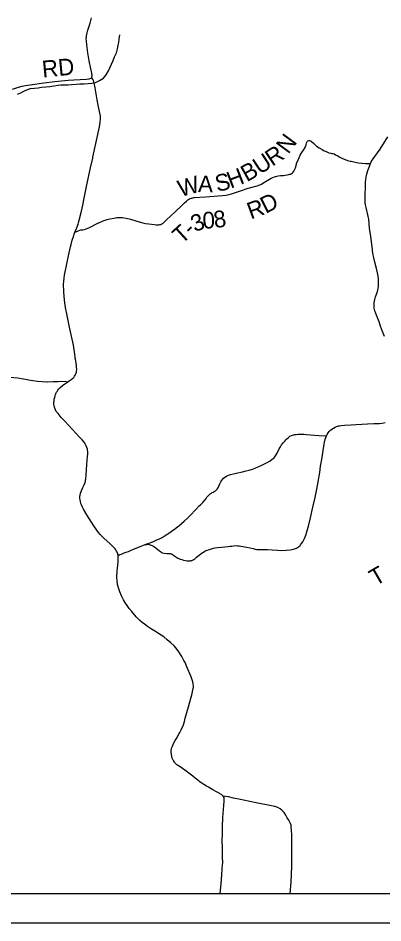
# Model space of a CAD drawing. Extents: x 0 to 34, y 0 to 22.
# Drawn here: x 3.772 to 5.01, y 14.105 to 17.181 of the extents above; entities that cross this region are included whole.
import ezdxf

# ---------------------------------------------------------------- set-up
doc = ezdxf.new("R2010")
doc.units = 0
for name, color, linetype in [('GM_X_County_Road', 7, 'Continuous'), ('GM_X_County_Road_Text', 7, 'Continuous'), ('GM_X_Major_River', 7, 'Continuous'), ('GM_X_State_Route', 7, 'Continuous'), ('GM_X_Township_Road', 7, 'Continuous'), ('GM_X_Township_Road_Text', 7, 'Continuous'), ('SH_Data', 7, 'Continuous')]:
    doc.layers.add(name, color=color, linetype=linetype)

msp = doc.modelspace()

# ---------------------------------------------------------------- linework, layer by layer
at = {"layer": 'GM_X_County_Road'}
msp.add_lwpolyline([(3.7528, 16.9393), (3.7733, 16.9459), (3.7853, 16.9491), (3.7975, 16.9518), (3.8129, 16.9542), (3.859, 16.9605), (3.896, 16.9651), (3.9423, 16.97), (3.9609, 16.9714), (4.0042, 16.9735), (4.0133, 16.9746), (4.017, 16.9757), (4.0195, 16.9769), (4.0216, 16.9792), (4.0225, 16.9812), (4.023, 16.9843), (4.0228, 16.9872), (4.0224, 16.9902), (4.0217, 16.9938), (4.0187, 17.0084), (4.0134, 17.0357), (4.0088, 17.0632), (4.0047, 17.0904), (4.0035, 17.1028), (4.0032, 17.1118), (4.0035, 17.1176), (4.0038, 17.1205), (4.0061, 17.1309), (4.0087, 17.1399), (4.0167, 17.1635), (4.0192, 17.1724), (4.0212, 17.1814)], dxfattribs=at)
at = {"layer": 'GM_X_Major_River'}
msp.add_lwpolyline([(3.7701, 16.9224), (3.7811, 16.9274), (3.7909, 16.9327), (3.8034, 16.9377), (3.8139, 16.9412), (3.8276, 16.9431), (3.8397, 16.9443), (3.8514, 16.9459), (3.8658, 16.9475), (3.8798, 16.9487), (3.8926, 16.9506), (3.9074, 16.9534), (3.9172, 16.9545), (3.9312, 16.9546), (3.9418, 16.9543), (3.9535, 16.9551), (3.9694, 16.9567), (3.9815, 16.9575), (3.9955, 16.9572), (4.0095, 16.9587), (4.0224, 16.9599), (4.0349, 16.9623), (4.0485, 16.9684), (4.0613, 16.9772), (4.0711, 16.9878), (4.079, 17.0015), (4.0839, 17.014), (4.0884, 17.0239), (4.0944, 17.0372), (4.0993, 17.0497), (4.1057, 17.0623), (4.1094, 17.0763), (4.112, 17.0884), (4.1135, 17.0979), (4.1154, 17.1097), (4.1172, 17.1241)], dxfattribs=at)
at = {"layer": 'GM_X_State_Route'}
msp.add_lwpolyline([(5.0158, 16.0988), (5.0089, 16.1158), (5.0021, 16.1335), (4.9971, 16.1482), (4.9904, 16.1659), (4.9862, 16.1764), (4.9827, 16.1858), (4.9807, 16.1946), (4.9801, 16.2007), (4.9799, 16.2068), (4.9803, 16.2129), (4.981, 16.2187), (4.9822, 16.2245), (4.9848, 16.2333), (4.9903, 16.2477), (4.993, 16.2565), (4.9942, 16.2625), (4.995, 16.2685), (4.9955, 16.2778), (4.9954, 16.2871), (4.9948, 16.2956), (4.9938, 16.3034), (4.9915, 16.3152), (4.9877, 16.33), (4.982, 16.351), (4.9786, 16.3662), (4.9759, 16.3816), (4.973, 16.4031), (4.9685, 16.4388), (4.965, 16.4664), (4.9618, 16.4973), (4.9604, 16.5065), (4.9592, 16.5125), (4.9531, 16.5366), (4.9511, 16.5459), (4.9502, 16.552), (4.9496, 16.5611), (4.9495, 16.5766), (4.9504, 16.6108), (4.951, 16.6232), (4.952, 16.6325), (4.9536, 16.6418), (4.9557, 16.6509), (4.9591, 16.6629), (4.9631, 16.6747), (4.9679, 16.6869), (4.9702, 16.692), (4.9731, 16.6976), (4.9765, 16.7028), (4.9821, 16.7104), (4.9916, 16.7226), (5.0005, 16.7353), (5.0271, 16.7772)], dxfattribs=at)
at = {"layer": 'GM_X_Township_Road'}
for points in [[(3.9407, 15.9449), (3.945, 15.9476), (3.9523, 15.9524), (3.9575, 15.9566), (3.9609, 15.9598), (3.9638, 15.9639), (3.9658, 15.9675), (3.968, 15.972), (3.9696, 15.9775), (3.9703, 15.9813), (3.9707, 15.9857), (3.9707, 15.9888), (3.9704, 15.9928), (3.97, 15.9986), (3.9685, 16.0088), (3.9677, 16.0148), (3.9664, 16.0213), (3.9659, 16.0252), (3.9653, 16.0297), (3.9645, 16.0382), (3.9626, 16.0536), (3.96, 16.0689), (3.9559, 16.09), (3.9467, 16.1308), (3.9384, 16.1703), (3.933, 16.1977), (3.9307, 16.2131), (3.9282, 16.2346), (3.9269, 16.2518), (3.9264, 16.2767), (3.9269, 16.286), (3.9281, 16.2983), (3.9294, 16.3076), (3.9369, 16.3455), (3.9425, 16.3724), (3.9502, 16.4034), (3.952, 16.4112), (3.9559, 16.4264), (3.9595, 16.4384), (3.9634, 16.4499), (3.9656, 16.4551), (3.9711, 16.4684), (3.9758, 16.4806), (3.9784, 16.4895), (3.9858, 16.5196), (3.9926, 16.5499), (3.9942, 16.5577), (3.9987, 16.5804), (4.0057, 16.6138), (4.0176, 16.6716), (4.025, 16.7053), (4.0256, 16.708), (4.0478, 16.8114), (4.0504, 16.8267), (4.0519, 16.839), (4.052, 16.8421), (4.0518, 16.8452), (4.0514, 16.8483), (4.0483, 16.8635), (4.0435, 16.8846), (4.04, 16.9027), (4.0329, 16.9435), (4.0295, 16.9594), (4.0272, 16.9687), (4.0255, 16.9735), (4.0236, 16.9767), (4.0216, 16.9792)], [(3.9656, 16.4551), (3.9671, 16.4548), (3.9695, 16.455), (3.9716, 16.4559), (3.9736, 16.4571), (3.9761, 16.4582), (3.9845, 16.4607), (3.9881, 16.4607), (3.9911, 16.4611), (3.9972, 16.4626), (4.003, 16.4647), (4.0116, 16.4684), (4.0449, 16.485), (4.0455, 16.4853), (4.0607, 16.4919), (4.0611, 16.492), (4.0675, 16.4942), (4.0739, 16.4961), (4.0829, 16.4983), (4.0982, 16.5013), (4.1074, 16.5028), (4.1135, 16.5033), (4.1197, 16.5035), (4.1259, 16.5031), (4.1321, 16.5022), (4.1381, 16.5009), (4.1532, 16.497), (4.1718, 16.4914), (4.1829, 16.488), (4.1949, 16.4849), (4.2041, 16.4832), (4.216, 16.4812), (4.2333, 16.4791), (4.2402, 16.4786), (4.2461, 16.4784), (4.2499, 16.4784), (4.2533, 16.479), (4.2564, 16.4798), (4.2592, 16.4811), (4.2644, 16.4844), (4.2668, 16.4864), (4.2715, 16.4905), (4.2758, 16.4949), (4.3051, 16.5225), (4.3274, 16.5439), (4.3363, 16.5525), (4.3431, 16.5589), (4.3479, 16.5628), (4.3505, 16.5645), (4.3532, 16.5661), (4.356, 16.5674), (4.3589, 16.5685), (4.3619, 16.5694), (4.3649, 16.5701), (4.3679, 16.5706), (4.371, 16.571), (4.4081, 16.5733), (4.466, 16.5775), (4.4783, 16.5793), (4.4875, 16.5812), (4.4932, 16.5828), (4.5066, 16.587), (4.5268, 16.5933), (4.5532, 16.6025), (4.583, 16.6112), (4.5918, 16.6142), (4.5975, 16.6166), (4.6029, 16.6195), (4.631, 16.6367), (4.6361, 16.6393), (4.6415, 16.6416), (4.6456, 16.643), (4.6497, 16.644), (4.6549, 16.6449), (4.6629, 16.6456), (4.6725, 16.6464), (4.691, 16.6492), (4.694, 16.6499), (4.6969, 16.651), (4.6998, 16.6526), (4.7034, 16.6553), (4.7056, 16.6577), (4.7073, 16.6603), (4.7088, 16.663), (4.712, 16.6696), (4.7129, 16.6722), (4.7162, 16.6843), (4.7172, 16.687), (4.7231, 16.7014), (4.7292, 16.7148), (4.7325, 16.7208), (4.7375, 16.7273), (4.7408, 16.7325), (4.7457, 16.7409), (4.7468, 16.744), (4.749, 16.7504), (4.7506, 16.7564), (4.7517, 16.7593), (4.7532, 16.7618), (4.7553, 16.764), (4.7581, 16.7652), (4.7611, 16.7652), (4.764, 16.764), (4.7665, 16.7624), (4.7751, 16.7542), (4.7844, 16.7461), (4.7932, 16.7398), (4.8033, 16.7338), (4.8088, 16.731), (4.8171, 16.727), (4.827, 16.7233), (4.8333, 16.7214), (4.8366, 16.7208), (4.8398, 16.7204), (4.8441, 16.7195), (4.8493, 16.7167), (4.8565, 16.7125), (4.8618, 16.7096), (4.8729, 16.7041), (4.8814, 16.7005), (4.8902, 16.6974), (4.8991, 16.6949), (4.9018, 16.6943), (4.9113, 16.6922), (4.9265, 16.6895), (4.9388, 16.688), (4.9512, 16.6871), (4.9605, 16.687), (4.9679, 16.6869)], [(3.7038, 15.9577), (3.7082, 15.9593), (3.7139, 15.9605), (3.7201, 15.9611), (3.7274, 15.9612), (3.7435, 15.9607), (3.7573, 15.9597), (3.7709, 15.9585), (3.7839, 15.9562), (3.797, 15.9534), (3.8144, 15.9501), (3.8375, 15.9472), (3.8533, 15.9452), (3.8681, 15.9447), (3.8702, 15.9446), (3.8904, 15.9457), (3.908, 15.9462), (3.9223, 15.9465), (3.9345, 15.9454), (3.9407, 15.9449)], [(4.4581, 14.2054), (4.4608, 14.2379), (4.4628, 14.2689), (4.4648, 14.2891), (4.466, 14.3025), (4.4662, 14.3108), (4.4658, 14.3278), (4.4651, 14.3589), (4.4649, 14.3864), (4.465, 14.4046), (4.4656, 14.4255), (4.466, 14.439), (4.4669, 14.458), (4.4672, 14.4639), (4.4697, 14.5041), (4.4712, 14.5195), (4.4717, 14.5255), (4.471, 14.5312), (4.4682, 14.536), (4.4656, 14.5389), (4.4629, 14.5407), (4.4555, 14.5452), (4.4538, 14.5462), (4.445, 14.5514), (4.433, 14.5581), (4.4267, 14.5617), (4.4185, 14.5663), (4.4118, 14.5704), (4.4027, 14.5754), (4.3957, 14.5799), (4.3896, 14.5843), (4.3815, 14.5907), (4.3729, 14.5975), (4.3654, 14.6039), (4.3599, 14.6079), (4.3418, 14.6212), (4.3251, 14.6335), (4.3132, 14.6413), (4.3109, 14.643), (4.3086, 14.6451), (4.3043, 14.6495), (4.3022, 14.6521), (4.2989, 14.6571), (4.2979, 14.6591), (4.2974, 14.6607), (4.2952, 14.6657), (4.2936, 14.6715), (4.2924, 14.6785), (4.2919, 14.6849), (4.2919, 14.692), (4.2927, 14.6972), (4.2937, 14.7013), (4.2958, 14.7062), (4.2982, 14.712), (4.3008, 14.7176), (4.3051, 14.7257), (4.3113, 14.7362), (4.314, 14.7412), (4.3185, 14.7488), (4.3207, 14.7526), (4.3254, 14.7616), (4.333, 14.7785), (4.3366, 14.7899), (4.3394, 14.8014), (4.3503, 14.8402), (4.3623, 14.8852), (4.3652, 14.8972), (4.3661, 14.902), (4.3666, 14.9061), (4.3669, 14.911), (4.3664, 14.9154), (4.3655, 14.9195), (4.3645, 14.9249), (4.3613, 14.9355), (4.3588, 14.9416), (4.3446, 14.9762), (4.3386, 14.9901), (4.3348, 14.9976), (4.3276, 15.011), (4.3172, 15.0266), (4.3084, 15.039), (4.3014, 15.0467), (4.2903, 15.0569), (4.2781, 15.0678), (4.2661, 15.0773), (4.257, 15.0835), (4.2488, 15.0888), (4.2382, 15.0955), (4.2251, 15.1039), (4.2105, 15.1135), (4.2008, 15.1206), (4.1932, 15.1262), (4.1854, 15.1328), (4.1787, 15.1398), (4.1728, 15.1461), (4.1685, 15.1515), (4.1579, 15.1636), (4.1491, 15.1745), (4.1422, 15.1839), (4.1362, 15.1924), (4.1296, 15.204), (4.1233, 15.2174), (4.1176, 15.2308), (4.1124, 15.2444), (4.1099, 15.2527), (4.1093, 15.2556), (4.109, 15.2588), (4.1085, 15.2647), (4.1074, 15.2832), (4.1072, 15.2888), (4.1076, 15.2946), (4.1083, 15.3025), (4.1092, 15.311), (4.1112, 15.3331), (4.1117, 15.3425), (4.1115, 15.3517), (4.1111, 15.3548), (4.1108, 15.3574), (4.1101, 15.3604), (4.1091, 15.3632), (4.108, 15.3661), (4.1063, 15.369), (4.1033, 15.3739), (4.1008, 15.377), (4.0963, 15.382), (4.084, 15.3942), (4.063, 15.413), (4.0569, 15.4188), (4.0507, 15.4254), (4.0449, 15.4326), (4.0392, 15.4401), (4.029, 15.455), (4.0046, 15.493), (3.9936, 15.512), (3.9892, 15.5203), (3.9865, 15.5263), (3.9845, 15.5315), (3.9831, 15.5377), (3.982, 15.5435), (3.9816, 15.5485), (3.9813, 15.5534), (3.9815, 15.5565), (3.9821, 15.5595), (3.9835, 15.5656), (3.9855, 15.5714), (3.9879, 15.5772), (3.992, 15.5855), (3.996, 15.5941), (3.9994, 15.6028), (4.0009, 15.6085), (4.0021, 15.6161), (4.0031, 15.6252), (4.0045, 15.6469), (4.0068, 15.6778), (4.0078, 15.6902), (4.0085, 15.6995), (4.0084, 15.7026), (4.0083, 15.7077), (4.0077, 15.7122), (4.007, 15.7162), (4.0052, 15.7211), (4.0026, 15.7267), (4.0001, 15.7319), (3.9956, 15.7392), (3.9889, 15.7475), (3.9807, 15.7569), (3.9309, 15.8111), (3.9183, 15.8239), (3.9074, 15.837), (3.9016, 15.8437), (3.8986, 15.8492), (3.8961, 15.8549), (3.8953, 15.8579), (3.894, 15.864), (3.8937, 15.8664), (3.8936, 15.8696), (3.8935, 15.8729), (3.8936, 15.8763), (3.894, 15.8804), (3.8948, 15.8854), (3.8961, 15.8915), (3.8974, 15.8965), (3.8991, 15.9013), (3.9002, 15.9043), (3.9013, 15.9067), (3.9024, 15.9089), (3.9039, 15.9118), (3.907, 15.9161), (3.9095, 15.9193), (3.9138, 15.9238), (3.923, 15.932), (3.9303, 15.9378), (3.9407, 15.9449)], [(4.7308, 15.3907), (4.7339, 15.3946), (4.7378, 15.401), (4.7434, 15.4122), (4.7479, 15.4238), (4.7518, 15.4352), (4.7584, 15.4587), (4.7641, 15.4823), (4.7722, 15.5183), (4.7796, 15.5509), (4.786, 15.5794), (4.7907, 15.6049), (4.7954, 15.6366), (4.7986, 15.6581), (4.8037, 15.6879), (4.8075, 15.711), (4.8109, 15.733), (4.8121, 15.7399), (4.8132, 15.7447), (4.8138, 15.747), (4.8145, 15.7501), (4.8185, 15.7608), (4.8212, 15.766), (4.8246, 15.7715), (4.828, 15.7757), (4.832, 15.7798), (4.837, 15.7837), (4.8421, 15.7871), (4.8479, 15.7906), (4.853, 15.7929), (4.8561, 15.794), (4.8591, 15.7948), (4.8622, 15.7953), (4.8684, 15.7959), (4.8794, 15.797), (4.9019, 15.7988), (4.9196, 15.7998), (4.9582, 15.8015), (4.9792, 15.8025), (4.9981, 15.8035), (5.0079, 15.8045), (5.0177, 15.8064)], [(4.2028, 15.3911), (4.2126, 15.3947), (4.2201, 15.3976), (4.225, 15.3994), (4.2289, 15.4011), (4.2341, 15.4032), (4.2384, 15.405), (4.2453, 15.4082), (4.2516, 15.4114), (4.2603, 15.4159), (4.2674, 15.4199), (4.274, 15.424), (4.2803, 15.428), (4.2835, 15.4301), (4.2915, 15.4355), (4.2958, 15.4387), (4.3018, 15.4431), (4.3087, 15.4484), (4.3173, 15.4555), (4.3268, 15.4635), (4.3357, 15.4715), (4.3463, 15.4815), (4.3544, 15.4895), (4.376, 15.5114), (4.3869, 15.5228), (4.3906, 15.5269), (4.3983, 15.5342), (4.4065, 15.543), (4.4101, 15.548), (4.4129, 15.5521), (4.4162, 15.5565), (4.4203, 15.5609), (4.4237, 15.5637), (4.4277, 15.5665), (4.4309, 15.5683), (4.434, 15.57), (4.4374, 15.5716), (4.4416, 15.5737), (4.4443, 15.5762), (4.4476, 15.5802), (4.4504, 15.5848), (4.4531, 15.5898), (4.4568, 15.5981), (4.4596, 15.6041), (4.4622, 15.6086), (4.4655, 15.613), (4.4695, 15.6172), (4.4737, 15.6206), (4.4796, 15.6242), (4.4857, 15.6268), (4.4928, 15.6292), (4.5026, 15.632), (4.5121, 15.6344), (4.5329, 15.6389), (4.5454, 15.6418), (4.5561, 15.6446), (4.5672, 15.6482), (4.5792, 15.6528), (4.5888, 15.6569), (4.5963, 15.6604), (4.6079, 15.6657), (4.6172, 15.6704), (4.6272, 15.676), (4.6343, 15.6812), (4.6405, 15.6868), (4.6456, 15.6935), (4.6496, 15.6999), (4.6581, 15.7166), (4.6619, 15.7234), (4.6663, 15.73), (4.6714, 15.737), (4.6766, 15.743), (4.6807, 15.7475), (4.6842, 15.751), (4.6893, 15.7559), (4.6946, 15.7597), (4.6994, 15.7623), (4.7106, 15.7652), (4.716, 15.7659), (4.7228, 15.7663), (4.733, 15.7665), (4.7418, 15.7663), (4.7507, 15.7659), (4.7776, 15.7637), (4.7928, 15.7625), (4.8185, 15.7608)], [(4.1111, 15.3548), (4.1175, 15.3572), (4.123, 15.3593), (4.1321, 15.3628), (4.1389, 15.3654), (4.1461, 15.3682), (4.1554, 15.372), (4.1749, 15.3801), (4.1892, 15.3862), (4.1948, 15.3885), (4.2028, 15.3911), (4.2088, 15.3922), (4.211, 15.3923), (4.213, 15.3924), (4.2152, 15.3922), (4.2171, 15.3918), (4.2202, 15.391), (4.2235, 15.3896), (4.2289, 15.3868), (4.2344, 15.3836), (4.2405, 15.3795), (4.2464, 15.3748), (4.2519, 15.3698), (4.255, 15.3674), (4.2585, 15.365), (4.2617, 15.3629), (4.2659, 15.3617), (4.2762, 15.3607), (4.2817, 15.3608), (4.2857, 15.3608), (4.2884, 15.3607), (4.2904, 15.3603), (4.2925, 15.3594), (4.2941, 15.3585), (4.2959, 15.3572), (4.299, 15.355), (4.3038, 15.3518), (4.3076, 15.3495), (4.3108, 15.3475), (4.314, 15.3456), (4.3177, 15.3439), (4.3218, 15.3421), (4.3275, 15.3403), (4.3336, 15.3388), (4.3399, 15.3375), (4.3456, 15.3365), (4.3497, 15.3361), (4.3523, 15.336), (4.3548, 15.3362), (4.3569, 15.3365), (4.3596, 15.337), (4.3621, 15.3377), (4.364, 15.3385), (4.366, 15.3395), (4.3687, 15.3412), (4.3715, 15.3433), (4.3775, 15.3481), (4.382, 15.3519), (4.3865, 15.3557), (4.3921, 15.36), (4.3967, 15.3633), (4.4007, 15.3659), (4.4057, 15.3687), (4.4101, 15.3709), (4.414, 15.3726), (4.4212, 15.3752), (4.428, 15.3773), (4.4345, 15.3789), (4.441, 15.3801), (4.4486, 15.3813), (4.4618, 15.3826), (4.473, 15.3834), (4.4845, 15.3845), (4.4915, 15.3855), (4.4971, 15.3865), (4.5043, 15.3875), (4.5104, 15.3878), (4.5164, 15.3875), (4.5224, 15.3868), (4.528, 15.3858), (4.5468, 15.3825), (4.5594, 15.38), (4.5693, 15.3778), (4.5769, 15.3761), (4.5818, 15.3752), (4.586, 15.3747), (4.5909, 15.3744), (4.5955, 15.3744), (4.5995, 15.3745), (4.6082, 15.3749), (4.618, 15.375), (4.6338, 15.3736), (4.6519, 15.3721), (4.6669, 15.3718), (4.6817, 15.3721), (4.6955, 15.3736), (4.7069, 15.3754), (4.7166, 15.3787), (4.7237, 15.3835), (4.7293, 15.3888), (4.7308, 15.3907)], [(4.695, 14.2054), (4.6987, 14.2439), (4.7005, 14.2975), (4.7007, 14.3147), (4.7011, 14.3345), (4.7004, 14.3632), (4.7007, 14.383), (4.7005, 14.4048), (4.6999, 14.4211), (4.6991, 14.4309), (4.6983, 14.4381), (4.6965, 14.4435), (4.6942, 14.4481), (4.6905, 14.4544), (4.6855, 14.4631), (4.681, 14.4714), (4.6744, 14.4808), (4.6666, 14.4887), (4.6615, 14.493), (4.6536, 14.4974), (4.6434, 14.5006), (4.6316, 14.5036), (4.5795, 14.5139), (4.5371, 14.5225), (4.5266, 14.5246), (4.503, 14.5297), (4.4856, 14.5335), (4.4759, 14.5352), (4.4682, 14.536)]]:
    msp.add_lwpolyline(points, dxfattribs=at)
at = {"layer": 'SH_Data'}
for p, q in [((1.9763, 14.2054), (8.7763, 14.2054)), ((1.8763, 14.1054), (8.8763, 14.1054))]:
    msp.add_line(p, q, dxfattribs=at)

# ---------------------------------------------------------------- texts
at = {"layer": 'GM_X_County_Road_Text'}
msp.add_text('RD', height=0.05682, rotation=5.4161, dxfattribs=at).set_placement((3.8555, 16.9789))
at = {"layer": 'GM_X_Township_Road_Text'}
for s, rotation, p in [('N', 53.6038, (4.6889, 16.716)), ('R', 33.6275, (4.6345, 16.6753)), ('U', 33.1411, (4.5922, 16.6477)), ('H', 20.9103, (4.4931, 16.6009)), ('B', 29.434, (4.5481, 16.6227)), ('W', 15.573, (4.323, 16.5723)), ('A', 358.5865, (4.3821, 16.5894)), ('S', 13.0687, (4.4476, 16.5898)), ('D', 26.9886, (4.612, 16.5152)), ('R', 20.2509, (4.5616, 16.4962)), ('3', 22.3677, (4.3718, 16.4525)), ('0', 3.1238, (4.3992, 16.4647)), ('8', 7.886, (4.4393, 16.4671)), ('T', 42.3688, (4.3274, 16.4105)), ('-', 42.9144, (4.3592, 16.4395)), ('T', 30.2398, (4.9847, 15.249))]:
    msp.add_text(s, height=0.0568, rotation=rotation, dxfattribs=at).set_placement(p)

doc.saveas('drawing.dxf')
